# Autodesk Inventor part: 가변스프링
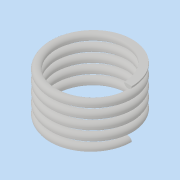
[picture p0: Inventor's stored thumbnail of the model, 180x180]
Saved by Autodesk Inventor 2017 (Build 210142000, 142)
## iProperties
Part Number: 가변스프링
Material: 일반
Document SubType Name: Modeling
Designer: mrc
Density: 1 g/cm^3
Appearance: 기본값
Mass: 0.953945 g
Surface Area: 19.566 cm^2
Volume: 0.953945 cm^3
Author: mrc
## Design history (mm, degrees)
sketch "스케치1"
  geometry: L1 (0, 0)-(10, 0); L2 (10, 0)-(10, 12.7); L3 (10, 12.7)-(0, 12.7); L4 (0, 12.7)-(0, 0); C1 r 1 at (10, 0)
  constraints: 8 end point, 2 parallel, 1 centre point, 1 coincident, 1 horizontal, 1 perpendicular
  dimensions: "d0" = 2 diameter of C1; "d1" = 12.7 distance of L3.end L1.start (derived); "d2" = 20 diameter of L2 L4
feature "코일1" sketch "스케치1" pitch "d3" = 10; turns "d5" = 5; dims "d4" = 12.7 (= d1), "d6" = 0, angle "d7" = 90 deg, angle "d8" = 90 deg, "d9" = 0, "d10" = 0
sketch "스케치2"
  geometry: L1 (-15, 12.7)-(35, 12.7); L2 (35, 12.7)-(35, 0); L3 (35, 0)-(-15, 0); L4 (-15, 0)-(-15, 12.7); C1 r 1 at (10, 0) reference; 5 further points
  constraints: 8 end point, 2 coincident, 2 midpoint, 2 parallel, 1 horizontal, 1 horizontal alignment, 1 perpendicular
  dimensions: "d11" = 50 distance of L1.start L1.end
extrude "돌출1" sketch "스케치2" stored distance "d12" = 0; taper "d13" = 0 deg
node "솔리드1"
